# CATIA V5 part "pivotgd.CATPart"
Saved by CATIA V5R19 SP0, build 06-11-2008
Part number: pivotgd
Publications: "e", "r"
Bounding box of the stored display mesh (mm): x -5 to 5, y 0 to 30, z -5 to 5
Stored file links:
  G:\EU_thinkMotion\CFAO_2010\MMS_groupe3\MMS_groupe3\A reprendre\evulliez\evulliez\pivotgd.CATPart
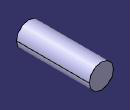
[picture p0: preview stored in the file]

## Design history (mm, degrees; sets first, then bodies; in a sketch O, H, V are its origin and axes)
Parameters
  e = 30 mm
  r = 5 mm
Body1 (main body)
  Sketch1 on zx-plane, origin (0, 0, 0), H (-1, 0, 0), V (0, 0, 1)
    circle A1 centre (0, 0) radius 5
    radius A1 = 5 {= r}
  Pad1: profile Sketch1, direction (0, 1, 0), length 30 {= e}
